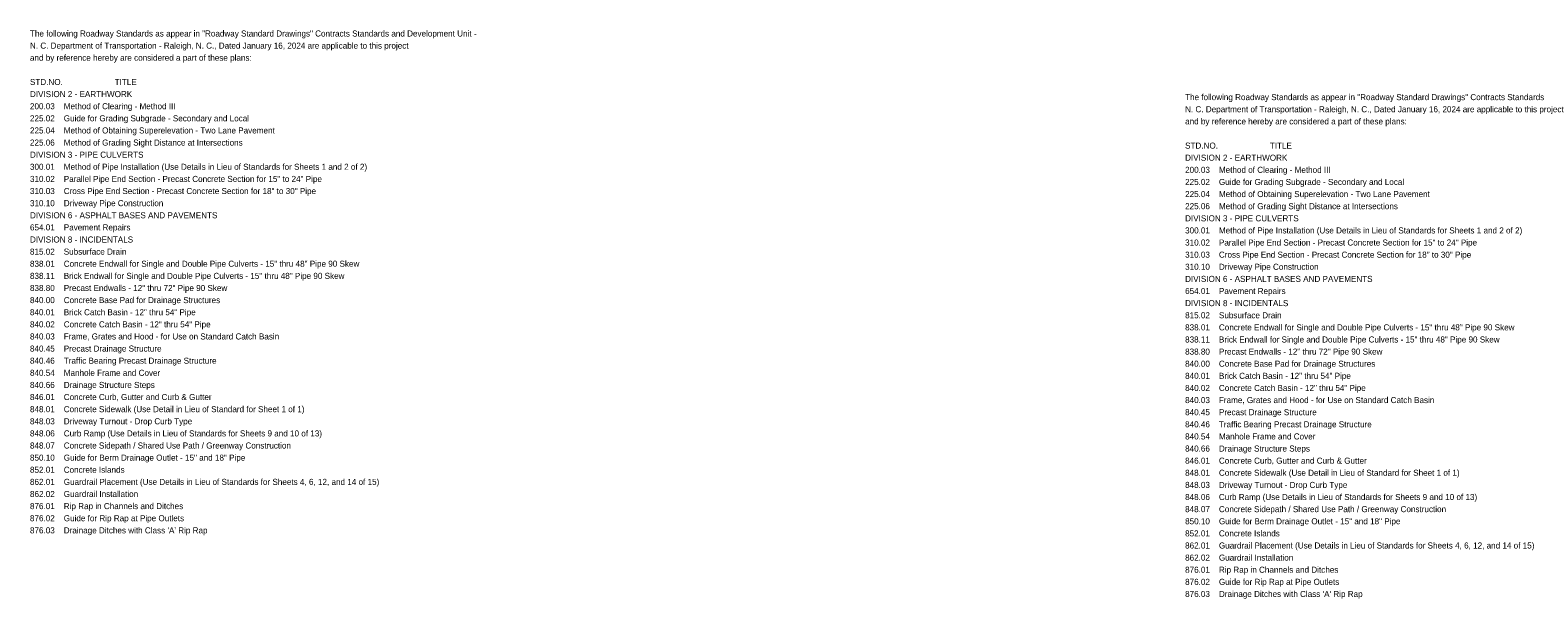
# Model space of a CAD drawing. Extents: x -1492 to 2447, y -56 to 1953.
# Drawn here: x -1492 to 0, y 1389 to 1953 of the extents above; entities that cross this region are included whole.
import ezdxf

# ---------------------------------------------------------------- set-up
doc = ezdxf.new("R2010")
doc.units = 0
doc.layers.add('Sheet Data Text CELL', color=7, linetype='Continuous')

msp = doc.modelspace()

# ---------------------------------------------------------------- texts
at = {"layer": 'Sheet Data Text CELL'}
for s, p in [('The following Roadway Standards as appear in "Roadway Standard Drawings" Contracts Standards and Development Unit -', (-1492.3, 1946.2)), ('N. C. Department of Transportation - Raleigh, N. C., Dated January 16, 2024 are applicable to this project', (-1492.3, 1934.2)), ('and by reference hereby are considered a part of these plans:', (-1492.3, 1922.2)), ('STD.NO.                       TITLE', (-1492.3, 1898.2)), ('200.03    Method of Clearing - Method III', (-1492.3, 1874.2)), ('DIVISION 2 - EARTHWORK', (-1492.3, 1886.2)), ('The following Roadway Standards as appear in "Roadway Standard Drawings" Contracts Standards and Development Unit -', (-349.3, 1883.2)), ('225.02    Guide for Grading Subgrade - Secondary and Local', (-1492.3, 1862.2)), ('and by reference hereby are considered a part of these plans:', (-349.3, 1859.2)), ('N. C. Department of Transportation - Raleigh, N. C., Dated January 16, 2024 are applicable to this project', (-349.3, 1871.2)), ('225.04    Method of Obtaining Superelevation - Two Lane Pavement', (-1492.3, 1850.2)), ('225.06    Method of Grading Sight Distance at Intersections', (-1492.3, 1838.2)), ('STD.NO.                       TITLE', (-349.3, 1835.2)), ('300.01    Method of Pipe Installation (Use Details in Lieu of Standards for Sheets 1 and 2 of 2)', (-1492.3, 1814.2)), ('DIVISION 3 - PIPE CULVERTS', (-1492.3, 1826.2)), ('DIVISION 2 - EARTHWORK', (-349.3, 1823.2)), ('310.02    Parallel Pipe End Section - Precast Concrete Section for 15" to 24" Pipe', (-1492.3, 1802.2)), ('200.03    Method of Clearing - Method III', (-349.3, 1811.2)), ('225.02    Guide for Grading Subgrade - Secondary and Local', (-349.3, 1799.2)), ('310.03    Cross Pipe End Section - Precast Concrete Section for 18" to 30" Pipe', (-1492.3, 1790.2)), ('225.04    Method of Obtaining Superelevation - Two Lane Pavement', (-349.3, 1787.2)), ('310.10    Driveway Pipe Construction', (-1492.3, 1778.2)), ('225.06    Method of Grading Sight Distance at Intersections', (-349.3, 1775.2)), ('654.01    Pavement Repairs', (-1492.3, 1754.2)), ('DIVISION 6 - ASPHALT BASES AND PAVEMENTS', (-1492.3, 1766.2)), ('DIVISION 3 - PIPE CULVERTS', (-349.3, 1763.2)), ('DIVISION 8 - INCIDENTALS', (-1492.3, 1742.2)), ('300.01    Method of Pipe Installation (Use Details in Lieu of Standards for Sheets 1 and 2 of 2)', (-349.3, 1751.2)), ('310.02    Parallel Pipe End Section - Precast Concrete Section for 15" to 24" Pipe', (-349.3, 1739.2)), ('815.02    Subsurface Drain', (-1492.3, 1730.2)), ('310.03    Cross Pipe End Section - Precast Concrete Section for 18" to 30" Pipe', (-349.3, 1727.2)), ('838.01    Concrete Endwall for Single and Double Pipe Culverts - 15" thru 48" Pipe 90 Skew', (-1492.3, 1718.2)), ('310.10    Driveway Pipe Construction', (-349.3, 1715.2)), ('838.11    Brick Endwall for Single and Double Pipe Culverts - 15" thru 48" Pipe 90 Skew', (-1492.3, 1706.2)), ('DIVISION 6 - ASPHALT BASES AND PAVEMENTS', (-349.3, 1703.2)), ('838.80    Precast Endwalls - 12" thru 72" Pipe 90 Skew', (-1492.3, 1694.2)), ('840.00    Concrete Base Pad for Drainage Structures', (-1492.3, 1682.2)), ('654.01    Pavement Repairs', (-349.3, 1691.2)), ('840.01    Brick Catch Basin - 12" thru 54" Pipe', (-1492.3, 1670.2)), ('815.02    Subsurface Drain', (-349.3, 1667.2)), ('DIVISION 8 - INCIDENTALS', (-349.3, 1679.2)), ('840.02    Concrete Catch Basin - 12" thru 54" Pipe', (-1492.3, 1658.2)), ('838.01    Concrete Endwall for Single and Double Pipe Culverts - 15" thru 48" Pipe 90 Skew', (-349.3, 1655.2)), ('840.03    Frame, Grates and Hood - for Use on Standard Catch Basin', (-1492.3, 1646.2)), ('838.11    Brick Endwall for Single and Double Pipe Culverts - 15" thru 48" Pipe 90 Skew', (-349.3, 1643.2)), ('840.45    Precast Drainage Structure', (-1492.3, 1634.2)), ('840.46    Traffic Bearing Precast Drainage Structure', (-1492.3, 1622.2)), ('838.80    Precast Endwalls - 12" thru 72" Pipe 90 Skew', (-349.3, 1631.2)), ('840.54    Manhole Frame and Cover', (-1492.3, 1610.2)), ('840.00    Concrete Base Pad for Drainage Structures', (-349.3, 1619.2)), ('840.01    Brick Catch Basin - 12" thru 54" Pipe', (-349.3, 1607.2)), ('840.66    Drainage Structure Steps', (-1492.3, 1598.2)), ('840.02    Concrete Catch Basin - 12" thru 54" Pipe', (-349.3, 1595.2)), ('846.01    Concrete Curb, Gutter and Curb & Gutter', (-1492.3, 1586.2)), ('840.03    Frame, Grates and Hood - for Use on Standard Catch Basin', (-349.3, 1583.2)), ('848.01    Concrete Sidewalk (Use Detail in Lieu of Standard for Sheet 1 of 1)', (-1492.3, 1574.2)), ('848.03    Driveway Turnout - Drop Curb Type', (-1492.3, 1562.2)), ('840.45    Precast Drainage Structure', (-349.3, 1571.2)), ('848.06    Curb Ramp (Use Details in Lieu of Standards for Sheets 9 and 10 of 13)', (-1492.3, 1550.2)), ('840.46    Traffic Bearing Precast Drainage Structure', (-349.3, 1559.2)), ('840.54    Manhole Frame and Cover', (-349.3, 1547.2)), ('848.07    Concrete Sidepath / Shared Use Path / Greenway Construction', (-1492.3, 1538.2)), ('840.66    Drainage Structure Steps', (-349.3, 1535.2)), ('850.10    Guide for Berm Drainage Outlet - 15" and 18" Pipe', (-1492.3, 1526.2)), ('846.01    Concrete Curb, Gutter and Curb & Gutter', (-349.3, 1523.2)), ('852.01    Concrete Islands', (-1492.3, 1514.2)), ('862.01    Guardrail Placement (Use Details in Lieu of Standards for Sheets 4, 6, 12, and 14 of 15)', (-1492.3, 1502.2)), ('848.01    Concrete Sidewalk (Use Detail in Lieu of Standard for Sheet 1 of 1)', (-349.3, 1511.2)), ('862.02    Guardrail Installation', (-1492.3, 1490.2)), ('848.03    Driveway Turnout - Drop Curb Type', (-349.3, 1499.2)), ('848.06    Curb Ramp (Use Details in Lieu of Standards for Sheets 9 and 10 of 13)', (-349.3, 1487.2)), ('876.01    Rip Rap in Channels and Ditches', (-1492.3, 1478.2)), ('848.07    Concrete Sidepath / Shared Use Path / Greenway Construction', (-349.3, 1475.2)), ('876.02    Guide for Rip Rap at Pipe Outlets', (-1492.3, 1466.2)), ('850.10    Guide for Berm Drainage Outlet - 15" and 18" Pipe', (-349.3, 1463.2)), ("876.03    Drainage Ditches with Class 'A' Rip Rap", (-1492.3, 1454.2)), ('852.01    Concrete Islands', (-349.3, 1451.2)), ('862.01    Guardrail Placement (Use Details in Lieu of Standards for Sheets 4, 6, 12, and 14 of 15)', (-349.3, 1439.2)), ('862.02    Guardrail Installation', (-349.3, 1427.2)), ('876.01    Rip Rap in Channels and Ditches', (-349.3, 1415.2)), ('876.02    Guide for Rip Rap at Pipe Outlets', (-349.3, 1403.2)), ("876.03    Drainage Ditches with Class 'A' Rip Rap", (-349.3, 1391.2))]:
    msp.add_text(s, height=6, dxfattribs=at).set_placement(p)

doc.saveas('drawing.dxf')
